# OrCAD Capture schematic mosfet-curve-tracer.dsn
size A; title: MOSFET Curve Tracer
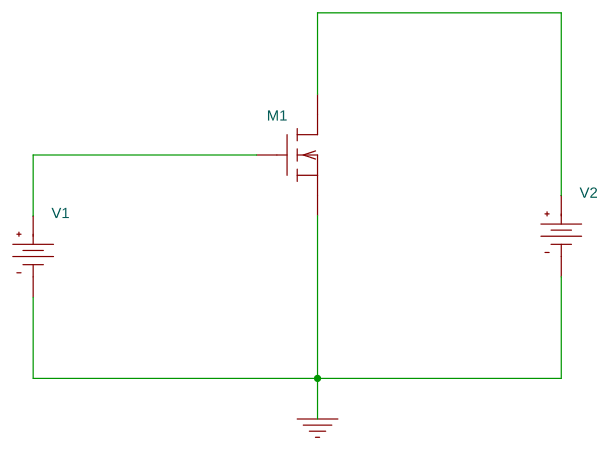
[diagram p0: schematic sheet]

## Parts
M1  MbreakN3
V1  VDC
V2  VDC

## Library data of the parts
M1 = MbreakN3
V1 V2 = VDC

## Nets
0: M1.0(s) V1.1(-) V2.1(-)
N14368: M1.2(d) V2.0(+)
N14402: M1.1(g) V1.0(+)
